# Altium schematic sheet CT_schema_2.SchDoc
size 454 x 387 mm
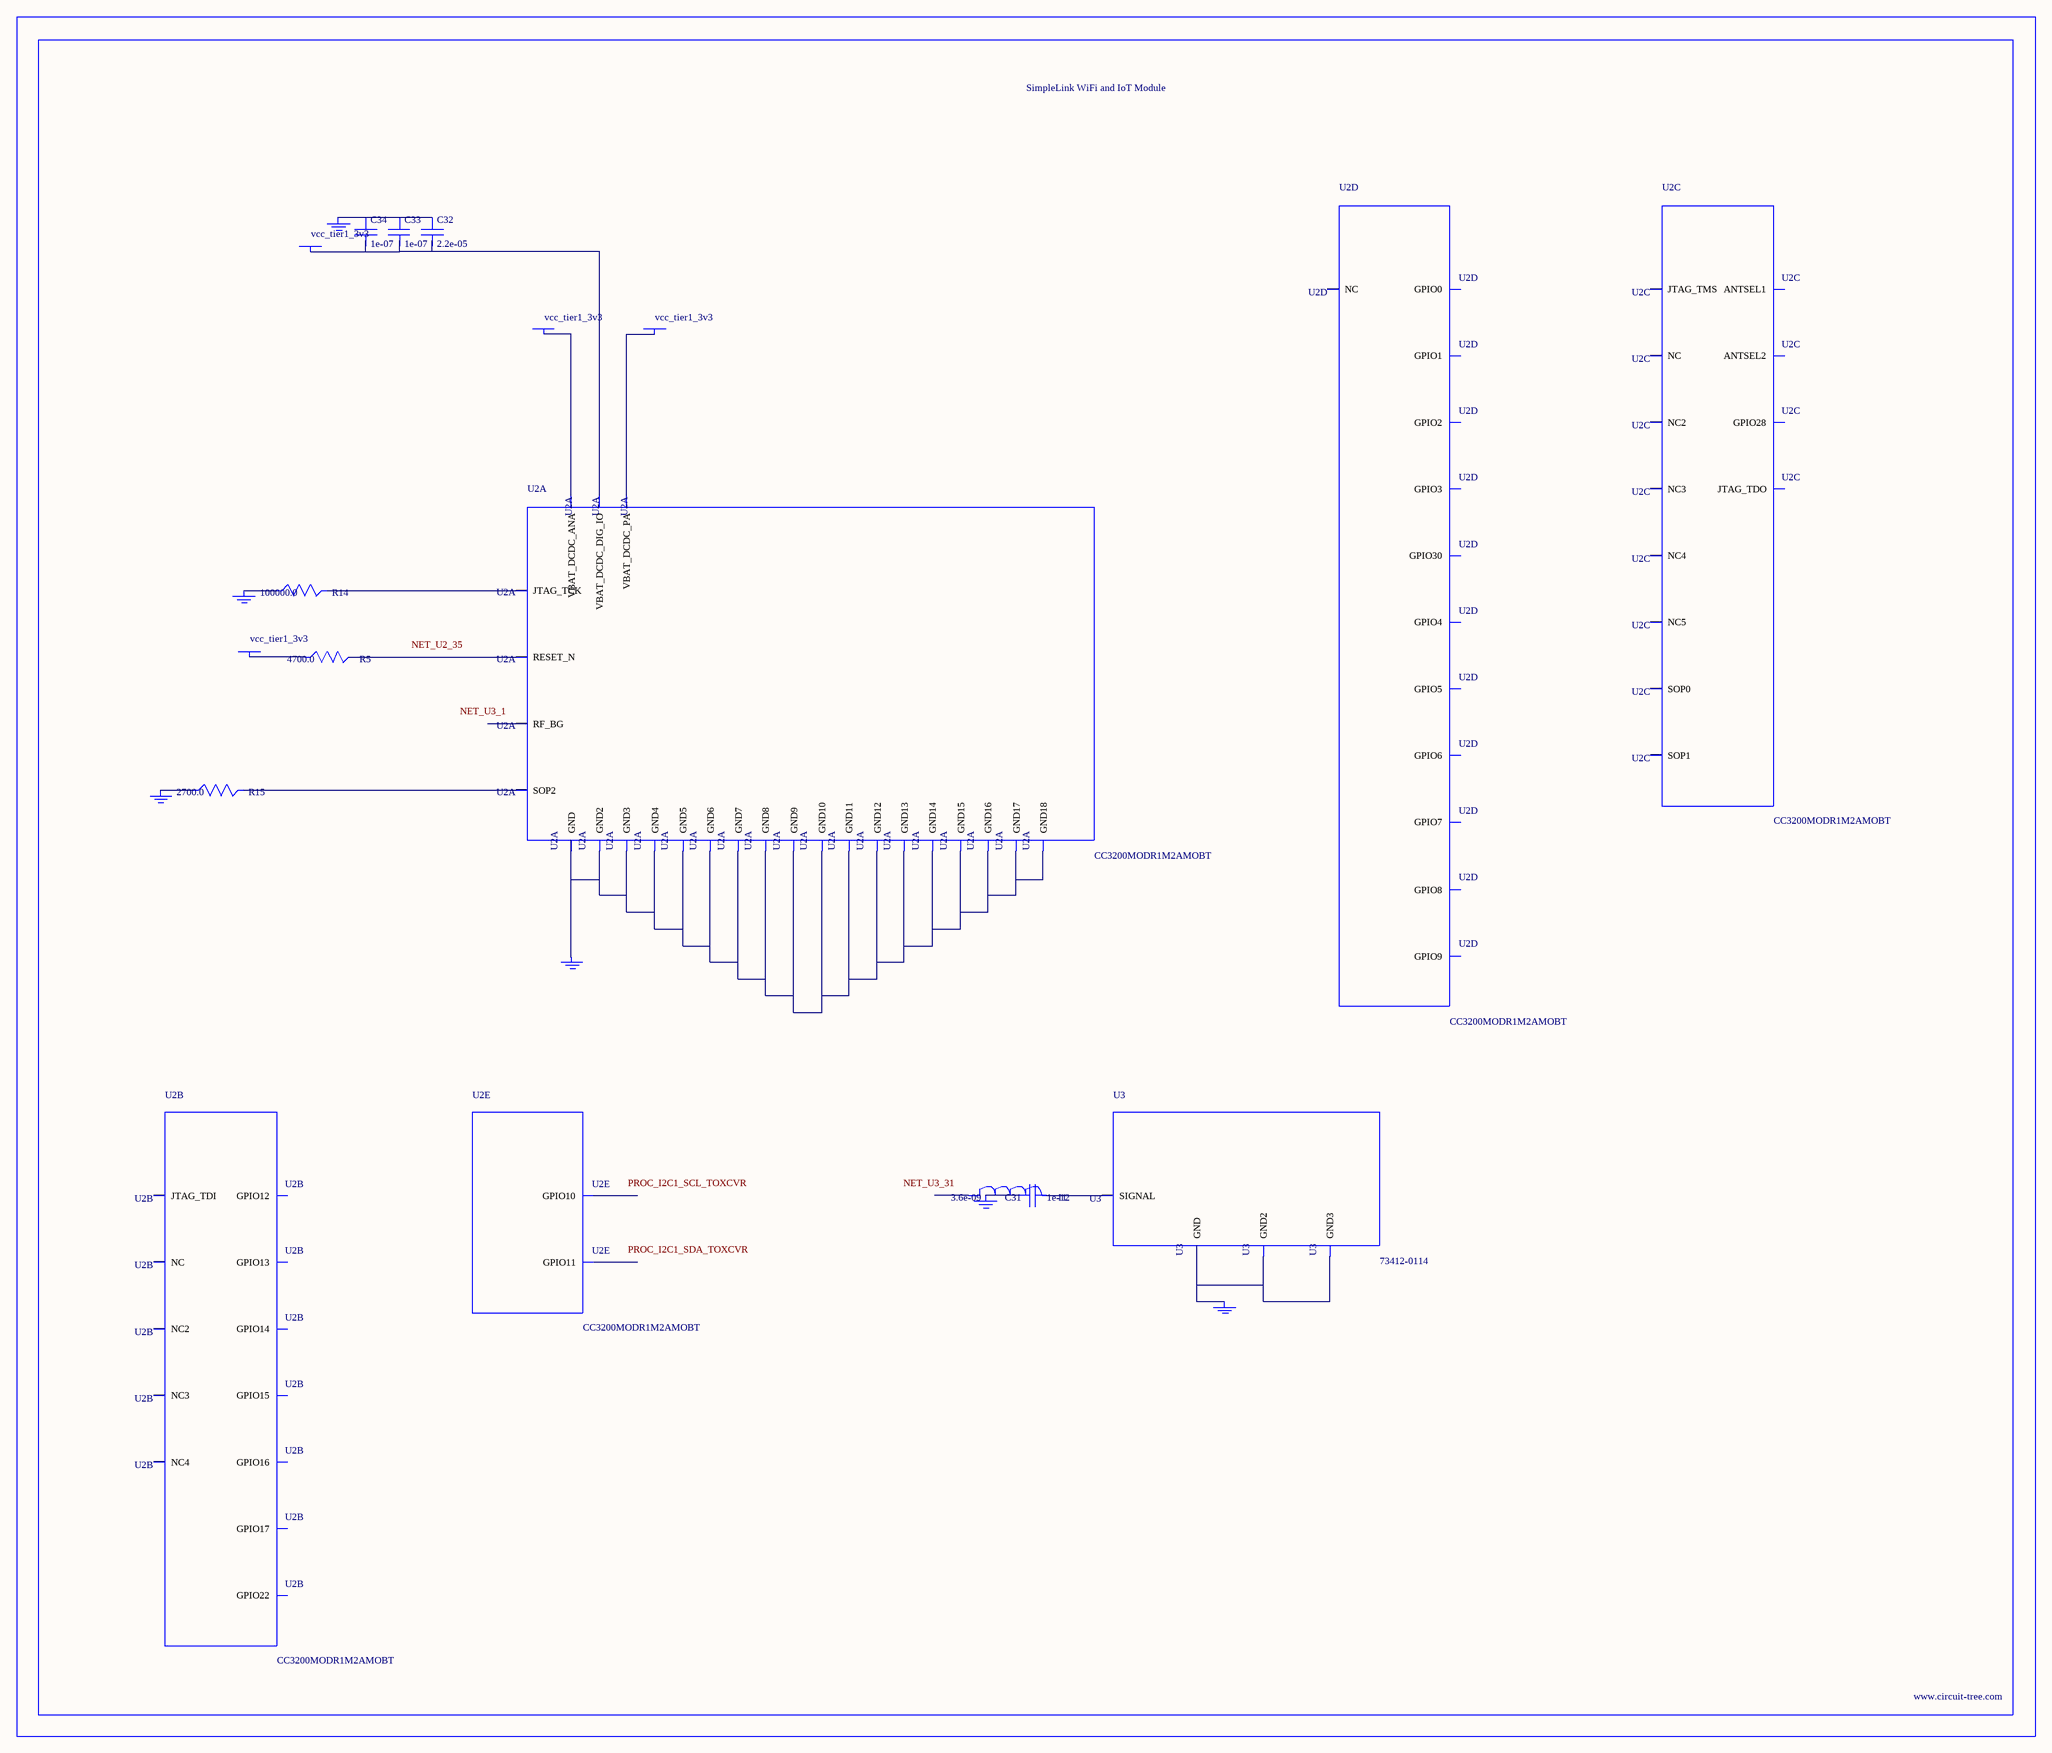
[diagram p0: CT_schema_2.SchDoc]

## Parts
BORDER1  (no value)
C31  1e-12  [C0402]
C32  2.2e-05  [C1210]
C33  1e-07  [C0402]
C34  1e-07  [C0402]
GND_INSTANCE_1_0  (no value)
GND_INSTANCE_1_1  (no value)
GND_INSTANCE_1_2  (no value)
GND_INSTANCE_1_3  (no value)
GND_INSTANCE_1_4  (no value)
GND_INSTANCE_1_5  (no value)
I1  3.6e-09  [C0402]
POWER_INSTANCE_1_0  vcc_tier1_3v3
POWER_INSTANCE_1_1  vcc_tier1_3v3
POWER_INSTANCE_1_2  vcc_tier1_3v3
POWER_INSTANCE_1_3  vcc_tier1_3v3
R5  4700.0  [R0603]
R14  100000.0  [R0603]
R15  2700.0  [R0603]
U2  CC3200MODR1M2AMOBT  [LGA63S127P16X13_2050X1750X150]  (parts A,B,C,D,E of 5)
U3  73412-0114  [COAXIAL_C]

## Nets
NetC31_1: C31.1 I1.2 U3.1(SIGNAL)
NetC31_2: C31.2 GND_INSTANCE_1_4.0(GND)
NetC32_1: C32.1 C33.1 C34.1 GND_INSTANCE_1_2.0(GND)
NetC32_2: C32.2 C33.2 C34.2 POWER_INSTANCE_1_2.0(PWR) U2.40(VBAT_DCDC_DIG_IO)
NetGND_INSTANCE_1_0_0: GND_INSTANCE_1_0.0(GND) R14.1
NetGND_INSTANCE_1_1_0: GND_INSTANCE_1_1.0(GND) R15.1
NetGND_INSTANCE_1_3_0: GND_INSTANCE_1_3.0(GND) U2.1(GND) U2.2(GND2) U2.16(GND3) U2.27(GND4) U2.28(GND5) U2.30(GND6) U2.32(GND7) U2.38(GND8) U2.43(GND9) U2.55(GND10) U2.56(GND11) U2.57(GND12) U2.58(GND13) U2.59(GND14) U2.60(GND15) U2.61(GND16) U2.62(GND17) U2.63(GND18)
NetGND_INSTANCE_1_5_0: GND_INSTANCE_1_5.0(GND) U3.2(GND) U3.3(GND2) U3.4(GND3)
NetPOWER_INSTANCE_1_0_0: POWER_INSTANCE_1_0.0(PWR) U2.36(VBAT_DCDC_ANA)
NetPOWER_INSTANCE_1_1_0: POWER_INSTANCE_1_1.0(PWR) U2.37(VBAT_DCDC_PA)
NetPOWER_INSTANCE_1_3_0: POWER_INSTANCE_1_3.0(PWR) R5.1
NetR5_2: R5.2 U2.35(RESET_N)
NetR14_2: R14.2 U2.21(JTAG_TCK)
NetR15_2: R15.2 U2.23(SOP2)

Not connected (* = marked no-connect by the designer): I1 1; U2 3(GPIO10) 4(GPIO11) 5(GPIO14) 6(GPIO15) 7(GPIO16) 8(GPIO17) 9(GPIO12) 10(GPIO13) 11(GPIO22) 12(JTAG_TDI) 13(NC) 14(NC2) 15(NC3) 17(NC4) 18(JTAG_TDO) 19(GPIO28) 20(NC) 22(JTAG_TMS) 24(SOP1) 25(ANTSEL1) 26(ANTSEL2) 29(NC2) 31(RF_BG) 33(NC3) 34(SOP0) 39(NC4) 41(NC5) 42(GPIO30) 44(GPIO0) 45(NC) 46(GPIO1) 47(GPIO2) 48(GPIO3) 49(GPIO4) 50(GPIO5) 51(GPIO6) 52(GPIO7) 53(GPIO8) 54(GPIO9)

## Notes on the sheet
- Labels drawn without touching a wire or pin: NET_U2_35, NET_U3_1, NET_U3_31, PROC_I2C1_SCL_TOXCVR, PROC_I2C1_SDA_TOXCVR

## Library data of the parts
BORDER1 = BORDER_PAGE1
C31 = C0402C109C3GACTU
C32 = C1210C224K5RACTU
C33 C34 = C0402C104K3RACTU
GND_INSTANCE_1_0-GND_INSTANCE_1_5 = GND
I1 = MCFT0BT3N6
POWER_INSTANCE_1_0-POWER_INSTANCE_1_3 = PWR
R5 = RC0603JR-074K7L
R14 = RC0603JR-07100KL
R15 = RC0603JR-072K7L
